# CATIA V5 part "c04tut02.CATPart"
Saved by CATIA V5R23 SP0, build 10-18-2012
Part number: c04tut02
Material "Aluminium": density 2710 kg/m3, Young's modulus 7e+10 Pa, Poisson ratio 0.346, thermal expansion 2.36e-05 1/K
Material "Aluminium": density 2710 kg/m3, Young's modulus 7e+10 Pa, Poisson ratio 0.346, thermal expansion 2.36e-05 1/K
Bounding box of the stored display mesh (mm): x 0 to 30, y -110 to 110, z -120 to 120
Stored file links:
  D:\APS\CATIA V5-6R-2013-Project\CATIA V5-6R2013_partfiles\Tutorials\c04_catia_v5-6r2013_tut\c04tut02.CATPart
  C:\Program Files\Dassault Systemes\B23\win_b64\startup\materials\Catalog.CATMaterial
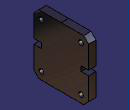
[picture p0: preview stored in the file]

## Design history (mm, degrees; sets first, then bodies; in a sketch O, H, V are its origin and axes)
Body1 (main body), material "Aluminium"
  Sketch1 on yz-plane, origin (0, 0, 0), H (0, 1, 0), V (0, 0, 1)
    construction line L1 (0, 0) -> (0, 117.7398)
    point P1 (0, 117.7398)
    axis line L2 (0, 0) -> (129.0807, 0)
    point P3 (0, 120)
    line L3 (0, 120) -> (90, 120)
    point P4 (90, 120)
    line L4 (90, 120) -> (110, 100)
    point P5 (110, 100)
    line L5 (110, 100) -> (110, 10)
    point P6 (110, 10)
    line L6 (110, 10) -> (80, 10)
    point P7 (80, 10)
    line L7 (80, 10) -> (80, 0)
    point P8 (80, 0)
    circle A1 centre (80, 90) radius 10
    point P9 (80, 90)
    point P10 (80, -10)
    point P11 (110, -10)
    line L8 (110, -10) -> (80, -10)
    point P12 (80, 0)
    line L9 (80, -10) -> (80, 0)
    point P13 (110, -100)
    line L10 (110, -100) -> (110, -10)
    circle A2 centre (80, -90) radius 10
    point P15 (90, -120)
    line L11 (90, -120) -> (110, -100)
    point P16 (0, -120)
    line L12 (0, -120) -> (90, -120)
    point P17 (0, -117.7398)
    point P18 (0, 0)
    construction line L13 (0, 0) -> (0, -117.7398)
    point P19 (-80, -10)
    point P20 (-110, -10)
    point P21 (-110, -100)
    point P23 (-90, -120)
    line L14 (-110, -10) -> (-80, -10)
    line L15 (-110, -100) -> (-110, -10)
    circle A3 centre (-80, -90) radius 10
    line L16 (-90, -120) -> (-110, -100)
    point P24 (0, -120)
    line L17 (0, -120) -> (-90, -120)
    point P25 (-80, 0)
    line L18 (-80, -10) -> (-80, 0)
    point P26 (-80, 0)
    point P27 (-80, 10)
    line L19 (-80, 10) -> (-80, 0)
    point P28 (-110, 10)
    line L20 (-110, 10) -> (-80, 10)
    point P29 (-110, 100)
    line L21 (-110, 100) -> (-110, 10)
    circle A4 centre (-80, 90) radius 10
    point P31 (-90, 120)
    line L22 (-90, 120) -> (-110, 100)
    point P32 (0, 120)
    line L23 (0, 120) -> (-90, 120)
    distance L15 L10 = 220
    distance L12 L3 = 240
    distance P9 L5 = 30
    distance P9 L3 = 30
    radius A1 = 10
    length L22 H = 20
    length L22 V = 20
    distance L8 L6 = 20
    distance L7 L19 = 160
    vertical: L1 V, L5 V, L7 V
    horizontal: L2 H, L3 H, L6 H
    coincidence: P3 L1, P8 L2, P3 P32, P8 P12, P16 P24, P25 P26
    symmetry: P7 P10 L2, P6 P11 L2, L6 L8 L2, P8 P12 L2, L7 L9 L2, P5 P13 L2, L5 L10 L2, A1 A2 L2, P4 P15 L2, L4 L11 L2, P3 P16 L2, L3 L12 L2, P1 P17 L2, O P18 L2, L1 L13 L2, P10 P19 L1, P11 P20 L1, P13 P21 L1, P15 P23 L1, L8 L14 L1, L10 L15 L1, A2 A3 L1, L11 L16 L1, P16 P24 L1, L12 L17 L1, P12 P25 L1, L9 L18 L1, P8 P26 L1, P7 P27 L1, L7 L19 L1, P6 P28 L1, L6 L20 L1, P5 P29 L1, L5 L21 L1, A1 A4 L1, P4 P31 L1, L4 L22 L1, P3 P32 L1, L3 L23 L1
  Pad1: profile Sketch1, direction (1, 0, 0), length 30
